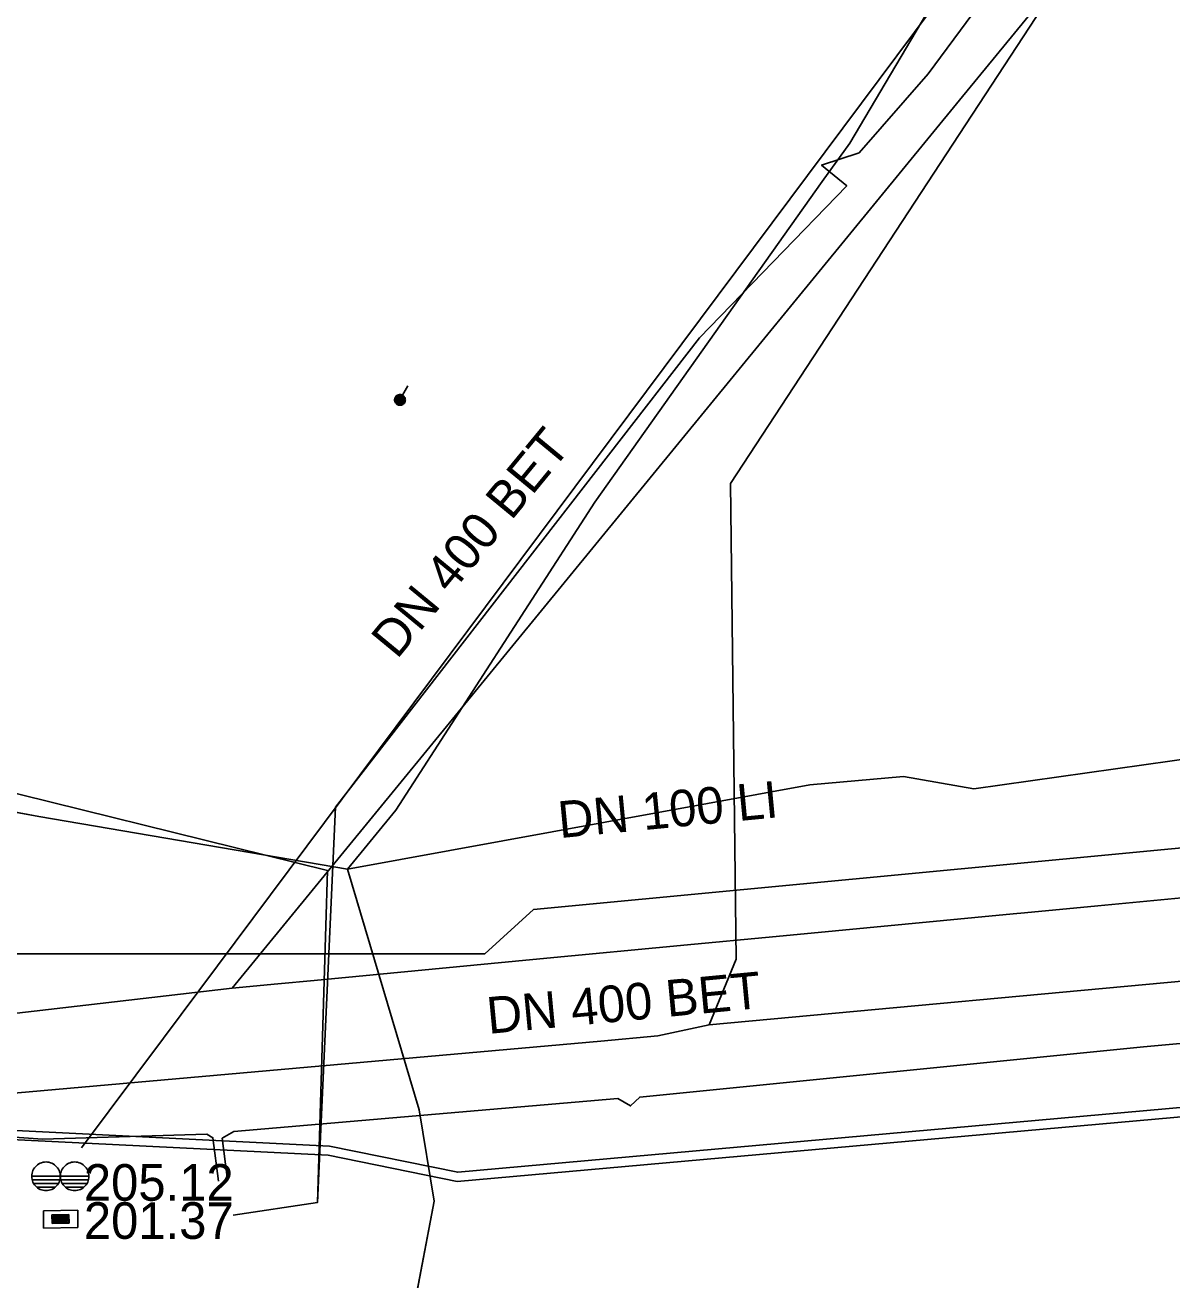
# Model space of a CAD drawing. Extents: x -596024 to -594475, y -1163820 to -1161957.
# Drawn here: x -595998.28 to -595973.24, y -1163008.77 to -1162981.37 of the extents above; entities that cross this region are included whole.
import ezdxf

# ---------------------------------------------------------------- set-up
doc = ezdxf.new("R2010")
doc.units = 0
for name, color, linetype in [('13', 7, 'Continuous'), ('Vrstva 12', 7, 'Continuous'), ('Vrstva 13', 7, 'Continuous'), ('Vrstva 15', 7, 'Continuous'), ('Vrstva 16', 7, 'Continuous'), ('Vrstva 25', 7, 'Continuous'), ('Vrstva 28', 7, 'Continuous'), ('Vrstva 42', 7, 'Continuous'), ('Vrstva 43', 7, 'Continuous'), ('Vrstva 51', 7, 'Continuous'), ('Vrstva 55', 7, 'Continuous'), ('Vrstva 9', 7, 'Continuous')]:
    doc.layers.add(name, color=color, linetype=linetype)

# ---------------------------------------------------------------- blocks, each defined once
blk = doc.blocks.new('NN500')
at = {"layer": '13'}
for points in [[(-0.001, -0.235), (0.023, -0.234), (0.048, -0.23), (0.071, -0.224), (0.094, -0.215), (0.116, -0.204), (0.137, -0.191), (0.156, -0.175), (0.173, -0.158), (0.189, -0.139), (0.202, -0.118), (0.213, -0.096), (0.222, -0.073), (0.229, -0.049), (0.232, -0.025), (0.234, 0), (0.232, 0.024), (0.229, 0.048), (0.222, 0.072), (0.213, 0.095), (0.202, 0.117), (0.189, 0.138), (0.173, 0.157), (0.156, 0.174), (0.137, 0.19), (0.116, 0.203), (0.094, 0.214), (0.071, 0.223), (0.048, 0.229), (0.023, 0.233), (-0.001, 0.235), (-0.026, 0.233), (-0.05, 0.229), (-0.074, 0.223), (-0.097, 0.214), (-0.119, 0.203), (-0.139, 0.19), (-0.158, 0.174), (-0.176, 0.157), (-0.191, 0.138), (-0.205, 0.117), (-0.216, 0.095), (-0.225, 0.072), (-0.231, 0.048), (-0.235, 0.024), (-0.236, 0), (-0.235, -0.025), (-0.231, -0.049), (-0.225, -0.073), (-0.216, -0.096), (-0.205, -0.118), (-0.191, -0.139), (-0.176, -0.158), (-0.158, -0.175), (-0.139, -0.191), (-0.119, -0.204), (-0.097, -0.215), (-0.074, -0.224), (-0.05, -0.23), (-0.026, -0.234), (-0.001, -0.235)], [(-0.001, -0.235), (0.023, -0.234), (0.048, -0.23), (0.071, -0.224), (0.094, -0.215), (0.116, -0.204), (0.137, -0.191), (0.156, -0.175), (0.173, -0.158), (0.189, -0.139), (0.202, -0.118), (0.213, -0.096), (0.222, -0.073), (0.229, -0.049), (0.232, -0.025), (0.234, 0), (0.232, 0.024), (0.229, 0.048), (0.222, 0.072), (0.213, 0.095), (0.202, 0.117), (0.189, 0.138), (0.173, 0.157), (0.156, 0.174), (0.137, 0.19), (0.116, 0.203), (0.094, 0.214), (0.071, 0.223), (0.048, 0.229), (0.023, 0.233), (-0.001, 0.235), (-0.026, 0.233), (-0.05, 0.229), (-0.074, 0.223), (-0.097, 0.214), (-0.119, 0.203), (-0.139, 0.19), (-0.158, 0.174), (-0.176, 0.157), (-0.191, 0.138), (-0.205, 0.117), (-0.216, 0.095), (-0.225, 0.072), (-0.231, 0.048), (-0.235, 0.024), (-0.236, 0), (-0.235, -0.025), (-0.231, -0.049), (-0.225, -0.073), (-0.216, -0.096), (-0.205, -0.118), (-0.191, -0.139), (-0.176, -0.158), (-0.158, -0.175), (-0.139, -0.191), (-0.119, -0.204), (-0.097, -0.215), (-0.074, -0.224), (-0.05, -0.23), (-0.026, -0.234), (-0.001, -0.235)], [(-0.001, -0.206), (0.02, -0.205), (0.041, -0.201), (0.062, -0.196), (0.082, -0.188), (0.101, -0.178), (0.12, -0.167), (0.136, -0.153), (0.151, -0.138), (0.165, -0.121), (0.177, -0.103), (0.186, -0.084), (0.194, -0.064), (0.2, -0.043), (0.203, -0.022), (0.204, 0), (0.203, 0.021), (0.2, 0.042), (0.194, 0.063), (0.186, 0.083), (0.177, 0.102), (0.165, 0.12), (0.151, 0.137), (0.136, 0.152), (0.12, 0.166), (0.101, 0.177), (0.082, 0.187), (0.062, 0.195), (0.041, 0.2), (0.02, 0.204), (-0.001, 0.205), (-0.023, 0.204), (-0.044, 0.2), (-0.065, 0.195), (-0.085, 0.187), (-0.104, 0.177), (-0.122, 0.166), (-0.139, 0.152), (-0.154, 0.137), (-0.167, 0.12), (-0.179, 0.102), (-0.189, 0.083), (-0.197, 0.063), (-0.202, 0.042), (-0.205, 0.021), (-0.207, 0), (-0.205, -0.022), (-0.202, -0.043), (-0.197, -0.064), (-0.189, -0.084), (-0.179, -0.103), (-0.167, -0.121), (-0.154, -0.138), (-0.139, -0.153), (-0.122, -0.167), (-0.104, -0.178), (-0.085, -0.188), (-0.065, -0.196), (-0.044, -0.201), (-0.023, -0.205), (-0.001, -0.206)], [(-0.001, -0.176), (0.017, -0.175), (0.035, -0.172), (0.053, -0.168), (0.07, -0.161), (0.087, -0.153), (0.102, -0.143), (0.116, -0.131), (0.129, -0.118), (0.141, -0.104), (0.151, -0.088), (0.159, -0.072), (0.166, -0.055), (0.171, -0.037), (0.174, -0.019), (0.175, 0), (0.174, 0.018), (0.171, 0.036), (0.166, 0.054), (0.159, 0.071), (0.151, 0.087), (0.141, 0.103), (0.129, 0.117), (0.116, 0.13), (0.102, 0.142), (0.087, 0.152), (0.07, 0.16), (0.053, 0.167), (0.035, 0.172), (0.017, 0.174), (-0.001, 0.175), (-0.02, 0.174), (-0.038, 0.172), (-0.056, 0.167), (-0.073, 0.16), (-0.089, 0.152), (-0.105, 0.142), (-0.119, 0.13), (-0.132, 0.117), (-0.143, 0.103), (-0.153, 0.087), (-0.162, 0.071), (-0.168, 0.054), (-0.173, 0.036), (-0.176, 0.018), (-0.177, 0), (-0.176, -0.019), (-0.173, -0.037), (-0.168, -0.055), (-0.162, -0.072), (-0.153, -0.088), (-0.143, -0.104), (-0.132, -0.118), (-0.119, -0.131), (-0.105, -0.143), (-0.089, -0.153), (-0.073, -0.161), (-0.056, -0.168), (-0.038, -0.172), (-0.02, -0.175), (-0.001, -0.176)], [(-0.001, -0.147), (0.014, -0.146), (0.029, -0.143), (0.044, -0.139), (0.058, -0.134), (0.072, -0.127), (0.085, -0.119), (0.097, -0.109), (0.107, -0.098), (0.117, -0.086), (0.125, -0.073), (0.132, -0.06), (0.138, -0.046), (0.142, -0.031), (0.144, -0.016), (0.145, 0), (0.144, 0.015), (0.142, 0.03), (0.138, 0.045), (0.132, 0.059), (0.125, 0.073), (0.117, 0.086), (0.107, 0.097), (0.097, 0.108), (0.085, 0.118), (0.072, 0.126), (0.058, 0.133), (0.044, 0.139), (0.029, 0.143), (0.014, 0.145), (-0.001, 0.146), (-0.017, 0.145), (-0.032, 0.143), (-0.046, 0.139), (-0.061, 0.133), (-0.074, 0.126), (-0.087, 0.118), (-0.099, 0.108), (-0.11, 0.097), (-0.119, 0.086), (-0.128, 0.073), (-0.135, 0.059), (-0.14, 0.045), (-0.144, 0.03), (-0.147, 0.015), (-0.147, 0), (-0.147, -0.016), (-0.144, -0.031), (-0.14, -0.046), (-0.135, -0.06), (-0.128, -0.073), (-0.119, -0.086), (-0.11, -0.098), (-0.099, -0.109), (-0.087, -0.119), (-0.074, -0.127), (-0.061, -0.134), (-0.046, -0.139), (-0.032, -0.143), (-0.017, -0.146), (-0.001, -0.147)], [(-0.001, -0.117), (0.011, -0.116), (0.023, -0.114), (0.035, -0.111), (0.046, -0.107), (0.057, -0.101), (0.067, -0.095), (0.077, -0.087), (0.085, -0.078), (0.093, -0.069), (0.1, -0.059), (0.105, -0.048), (0.11, -0.036), (0.113, -0.025), (0.115, -0.013), (0.115, 0), (0.115, 0.012), (0.113, 0.024), (0.11, 0.036), (0.105, 0.047), (0.1, 0.058), (0.093, 0.068), (0.085, 0.078), (0.077, 0.086), (0.067, 0.094), (0.057, 0.101), (0.046, 0.106), (0.035, 0.11), (0.023, 0.114), (0.011, 0.116), (-0.001, 0.116), (-0.013, 0.116), (-0.025, 0.114), (-0.037, 0.11), (-0.049, 0.106), (-0.059, 0.101), (-0.07, 0.094), (-0.079, 0.086), (-0.088, 0.078), (-0.096, 0.068), (-0.102, 0.058), (-0.108, 0.047), (-0.112, 0.036), (-0.115, 0.024), (-0.117, 0.012), (-0.118, 0), (-0.117, -0.013), (-0.115, -0.025), (-0.112, -0.036), (-0.108, -0.048), (-0.102, -0.059), (-0.096, -0.069), (-0.088, -0.078), (-0.079, -0.087), (-0.07, -0.095), (-0.059, -0.101), (-0.049, -0.107), (-0.037, -0.111), (-0.025, -0.114), (-0.013, -0.116), (-0.001, -0.117)], [(-0.001, -0.087), (0.008, -0.087), (0.017, -0.085), (0.026, -0.083), (0.034, -0.08), (0.042, -0.076), (0.05, -0.071), (0.057, -0.065), (0.063, -0.059), (0.069, -0.051), (0.074, -0.044), (0.078, -0.036), (0.081, -0.027), (0.084, -0.019), (0.085, -0.01), (0.086, 0), (0.085, 0.009), (0.084, 0.018), (0.081, 0.026), (0.078, 0.035), (0.074, 0.043), (0.069, 0.051), (0.063, 0.058), (0.057, 0.064), (0.05, 0.07), (0.042, 0.075), (0.034, 0.079), (0.026, 0.082), (0.017, 0.085), (0.008, 0.086), (-0.001, 0.087), (-0.01, 0.086), (-0.019, 0.085), (-0.028, 0.082), (-0.037, 0.079), (-0.045, 0.075), (-0.052, 0.07), (-0.059, 0.064), (-0.066, 0.058), (-0.072, 0.051), (-0.077, 0.043), (-0.081, 0.035), (-0.084, 0.026), (-0.086, 0.018), (-0.088, 0.009), (-0.088, 0), (-0.088, -0.01), (-0.086, -0.019), (-0.084, -0.027), (-0.081, -0.036), (-0.077, -0.044), (-0.072, -0.052), (-0.066, -0.059), (-0.059, -0.065), (-0.052, -0.071), (-0.045, -0.076), (-0.037, -0.08), (-0.028, -0.083), (-0.019, -0.085), (-0.01, -0.087), (-0.001, -0.087)], [(-0.001, -0.058), (0.005, -0.057), (0.011, -0.056), (0.016, -0.055), (0.022, -0.053), (0.027, -0.05), (0.032, -0.047), (0.037, -0.043), (0.041, -0.039), (0.045, -0.034), (0.048, -0.029), (0.051, -0.024), (0.053, -0.018), (0.055, -0.012), (0.056, -0.006), (0.056, 0), (0.056, 0.006), (0.055, 0.011), (0.053, 0.017), (0.051, 0.023), (0.048, 0.028), (0.045, 0.033), (0.041, 0.038), (0.037, 0.042), (0.032, 0.046), (0.027, 0.049), (0.022, 0.052), (0.016, 0.054), (0.011, 0.056), (0.005, 0.057), (-0.001, 0.057), (-0.007, 0.057), (-0.013, 0.056), (-0.019, 0.054), (-0.025, 0.052), (-0.03, 0.049), (-0.035, 0.046), (-0.04, 0.042), (-0.044, 0.038), (-0.048, 0.033), (-0.051, 0.028), (-0.054, 0.023), (-0.056, 0.017), (-0.057, 0.011), (-0.058, 0.006), (-0.059, 0), (-0.058, -0.006), (-0.057, -0.012), (-0.056, -0.018), (-0.054, -0.024), (-0.051, -0.029), (-0.048, -0.034), (-0.044, -0.039), (-0.04, -0.043), (-0.035, -0.047), (-0.03, -0.05), (-0.025, -0.053), (-0.019, -0.055), (-0.013, -0.056), (-0.007, -0.057), (-0.001, -0.058)], [(-0.001, -0.028), (0.002, -0.028), (0.005, -0.028), (0.007, -0.027), (0.01, -0.026), (0.013, -0.024), (0.015, -0.023), (0.017, -0.021), (0.019, -0.019), (0.021, -0.017), (0.023, -0.014), (0.024, -0.012), (0.025, -0.009), (0.026, -0.006), (0.026, -0.003), (0.027, 0), (0.026, 0.002), (0.026, 0.005), (0.025, 0.008), (0.024, 0.011), (0.023, 0.013), (0.021, 0.016), (0.019, 0.018), (0.017, 0.02), (0.015, 0.022), (0.013, 0.024), (0.01, 0.025), (0.007, 0.026), (0.005, 0.027), (0.002, 0.027), (-0.001, 0.027), (-0.004, 0.027), (-0.007, 0.027), (-0.01, 0.026), (-0.012, 0.025), (-0.015, 0.024), (-0.018, 0.022), (-0.02, 0.02), (-0.022, 0.018), (-0.024, 0.016), (-0.025, 0.013), (-0.027, 0.011), (-0.028, 0.008), (-0.028, 0.005), (-0.029, 0.002), (-0.029, 0), (-0.029, -0.003), (-0.028, -0.006), (-0.028, -0.009), (-0.027, -0.012), (-0.025, -0.014), (-0.024, -0.017), (-0.022, -0.019), (-0.02, -0.021), (-0.018, -0.023), (-0.015, -0.024), (-0.012, -0.026), (-0.01, -0.027), (-0.007, -0.028), (-0.004, -0.028), (-0.001, -0.028)], [(0.234, 0), (0.704, 0)]]:
    blk.add_lwpolyline(points, dxfattribs=at)
blk = doc.blocks.new('NN450')
at = {"layer": '13'}
for points in [[(0, 0), (-0.003, 0.065), (-0.013, 0.13), (-0.031, 0.193), (-0.054, 0.254), (-0.084, 0.312), (-0.119, 0.367), (-0.161, 0.418), (-0.207, 0.464), (-0.258, 0.505), (-0.313, 0.541), (-0.371, 0.571), (-0.432, 0.594), (-0.495, 0.611), (-0.559, 0.621), (-0.625, 0.625), (-0.69, 0.621), (-0.755, 0.611), (-0.818, 0.594), (-0.879, 0.571), (-0.938, 0.541), (-0.992, 0.505), (-1.043, 0.464), (-1.089, 0.418), (-1.13, 0.367), (-1.166, 0.312), (-1.196, 0.254), (-1.219, 0.193), (-1.236, 0.13), (-1.246, 0.065), (-1.25, 0), (-1.246, -0.066), (-1.236, -0.13), (-1.219, -0.193), (-1.196, -0.255), (-1.166, -0.313), (-1.13, -0.368), (-1.089, -0.419), (-1.043, -0.465), (-0.992, -0.506), (-0.937, -0.542), (-0.879, -0.571), (-0.818, -0.595), (-0.755, -0.612), (-0.69, -0.622), (-0.625, -0.625), (-0.559, -0.622), (-0.495, -0.612), (-0.432, -0.595), (-0.37, -0.571), (-0.312, -0.542), (-0.258, -0.506), (-0.207, -0.465), (-0.161, -0.419), (-0.119, -0.368), (-0.084, -0.313), (-0.054, -0.254), (-0.031, -0.193), (-0.013, -0.13), (-0.003, -0.066), (0, 0)], [(1.25, 0), (1.247, 0.065), (1.237, 0.13), (1.219, 0.193), (1.196, 0.254), (1.166, 0.312), (1.131, 0.367), (1.089, 0.418), (1.043, 0.464), (0.992, 0.505), (0.937, 0.541), (0.879, 0.571), (0.818, 0.594), (0.755, 0.611), (0.691, 0.621), (0.625, 0.625), (0.56, 0.621), (0.495, 0.611), (0.432, 0.594), (0.371, 0.571), (0.312, 0.541), (0.258, 0.505), (0.207, 0.464), (0.161, 0.418), (0.12, 0.367), (0.084, 0.312), (0.054, 0.254), (0.031, 0.193), (0.014, 0.13), (0.004, 0.065), (0, 0), (0.004, -0.066), (0.014, -0.13), (0.031, -0.193), (0.054, -0.255), (0.084, -0.313), (0.12, -0.368), (0.161, -0.419), (0.207, -0.465), (0.258, -0.506), (0.313, -0.542), (0.371, -0.571), (0.432, -0.595), (0.495, -0.612), (0.56, -0.622), (0.625, -0.625), (0.691, -0.622), (0.755, -0.612), (0.818, -0.595), (0.88, -0.571), (0.938, -0.542), (0.992, -0.506), (1.043, -0.465), (1.089, -0.419), (1.131, -0.368), (1.166, -0.313), (1.196, -0.254), (1.219, -0.193), (1.237, -0.13), (1.247, -0.066), (1.25, 0)], [(-1.25, 0), (1.25, 0)], [(-1.23, -0.158), (-0.02, -0.158)], [(-1.161, -0.315), (-0.088, -0.315)], [(-1.033, -0.473), (-0.216, -0.473)], [(0.02, -0.158), (1.23, -0.158)], [(0.089, -0.315), (1.162, -0.315)], [(0.217, -0.473), (1.034, -0.473)]]:
    blk.add_lwpolyline(points, dxfattribs=at)
blk = doc.blocks.new('NN620')
at = {"layer": 'Vrstva 28'}
for points in [[(0.752, 0.004), (-0.748, 0.004)], [(-0.748, 0.004), (-0.748, -0.746)], [(0.752, -0.746), (0.752, 0.004)], [(0.368, -0.18), (-0.376, -0.18)], [(-0.376, -0.18), (-0.376, -0.558)], [(0.321, -0.227), (-0.329, -0.227)], [(-0.329, -0.227), (-0.329, -0.51)], [(-0.329, -0.51), (0.321, -0.51)], [(0.274, -0.274), (-0.281, -0.274)], [(-0.281, -0.274), (-0.281, -0.463)], [(-0.281, -0.463), (0.274, -0.463)], [(0.227, -0.321), (-0.234, -0.321)], [(-0.234, -0.321), (-0.234, -0.416)], [(-0.234, -0.416), (0.227, -0.416)], [(-0.193, -0.369), (0.185, -0.369)], [(0.227, -0.416), (0.227, -0.321)], [(0.274, -0.463), (0.274, -0.274)], [(0.321, -0.51), (0.321, -0.227)], [(0.368, -0.558), (0.368, -0.18)], [(-0.748, -0.746), (0.752, -0.746)], [(-0.376, -0.558), (0.368, -0.558)]]:
    blk.add_lwpolyline(points, dxfattribs=at)

msp = doc.modelspace()

# ---------------------------------------------------------------- linework, layer by layer
at = {"layer": 'Vrstva 13'}
msp.add_lwpolyline([(-596022.832, -1162998.021), (-596005.425, -1163001.297), (-596003.66, -1163001.651), (-595998.732, -1163001.652), (-595988.242, -1163001.653), (-595987.182, -1163000.686), (-595973.244, -1162999.36), (-595961.169, -1162998.229), (-595948.572, -1162997.021), (-595937.132, -1162995.978)], dxfattribs=at)
at = {"layer": 'Vrstva 16'}
for points in [[(-595982.75, -1163001.77), (-595982.88, -1162991.38), (-595972.32, -1162975.27), (-595958.95, -1162954.17)], [(-596007.93, -1163004.08), (-596001.98, -1163005), (-595985.71, -1163003.56), (-595984.46, -1163003.44), (-595983.34, -1163003.2), (-595971.99, -1163002.15), (-595963.48, -1163001.34), (-595954.05, -1163000.5), (-595949.2, -1163000.21), (-595946.71, -1162999.77), (-595933.26, -1162998.54), (-595930.88, -1162998.19), (-595929.42, -1162998.06), (-595910.58, -1162996.4), (-595906.55, -1162996.02), (-595900.64, -1162995.37)], [(-595983.34, -1163003.2), (-595982.75, -1163001.77)]]:
    msp.add_lwpolyline(points, dxfattribs=at)
at = {"layer": 'Vrstva 25'}
for p, q in [((-595976.499, -1162977.581), (-595980.271, -1162983.953)), ((-595980.271, -1162983.953), (-595980.876, -1162984.787)), ((-595980.876, -1162984.787), (-595985.837, -1162991.79)), ((-595985.837, -1162991.79), (-595990.189, -1162998.516)), ((-595977.563, -1162998.049), (-595967.259, -1162996.597)), ((-596003.484, -1162997.626), (-595997.979, -1162998.655)), ((-595981.147, -1162997.962), (-595979.1, -1162997.779)), ((-595979.1, -1162997.779), (-595977.563, -1162998.049)), ((-595991.239, -1162999.804), (-595981.147, -1162997.962)), ((-595997.979, -1162998.655), (-595991.239, -1162999.804)), ((-595990.189, -1162998.516), (-595991.239, -1162999.804)), ((-595991.239, -1162999.804), (-595989.673, -1163005.056)), ((-595989.673, -1163005.056), (-595989.347, -1163007.053)), ((-595989.347, -1163007.053), (-595990.276, -1163011.905))]:
    msp.add_line(p, q, dxfattribs=at)
msp.add_lwpolyline([(-596024.42, -1162985.641), (-596023.237, -1162985.609), (-596020.944, -1162985.706), (-596022.205, -1162989.863), (-596022.376, -1162991.551), (-596022.268, -1162992.371), (-596019.799, -1162994.146), (-596014.487, -1162995.095), (-596007.51, -1162996.568), (-596003.484, -1162997.626), (-595997.979, -1162998.655), (-595991.239, -1162999.804), (-595989.673, -1163005.056), (-595989.347, -1163007.053), (-595990.276, -1163011.905)], dxfattribs=at)
at = {"layer": 'Vrstva 42'}
for points in [[(-596001.179, -1163005.878), (-596001.118, -1163005.375), (-595991.637, -1163005.851), (-595988.834, -1163006.419), (-595972.4, -1163004.95), (-595963.67, -1163004.02), (-595944.189, -1163002.2), (-595944.99, -1162995), (-595945.587, -1162992.845), (-595945.86, -1162992.44), (-595946.275, -1162991.8), (-595946.479, -1162991.626)], [(-596000.981, -1163005.902), (-596000.942, -1163005.585), (-595991.663, -1163006.049), (-595988.846, -1163006.621), (-595972.38, -1163005.15), (-595963.65, -1163004.22), (-595944.171, -1163002.4), (-595942.78, -1163002.28), (-595931.44, -1163001.28), (-595920.349, -1162999.982), (-595919.824, -1163004.454), (-595919.709, -1163004.569), (-595919.624, -1163004.448), (-595920.153, -1162999.937), (-595919.2, -1162999.61), (-595906.12, -1162998.78), (-595905.29, -1162998.32), (-595901.71, -1162997.86), (-595900.28, -1162998.15), (-595894.13, -1162997.39)]]:
    msp.add_lwpolyline(points, dxfattribs=at)
at = {"layer": 'Vrstva 51'}
msp.add_lwpolyline([(-595997.05, -1163005.887), (-595995.26, -1163003.49), (-595977.679, -1162979.94), (-595958.057, -1162953.079)], dxfattribs=at)
at = {"layer": 'Vrstva 55'}
for points in [[(-595993.737, -1163007.36), (-595991.896, -1163007.08), (-595991.68, -1162999.83), (-596000.4, -1162997.68), (-596012.68, -1162994.73), (-596018.57, -1162992.95), (-596015.38, -1162970.85), (-596018.2, -1162967.54), (-596017.59, -1162962.68), (-596013.46, -1162940.69), (-596008.27, -1162917.84), (-596004.5, -1162911.68)], [(-595993.737, -1163007.36), (-595991.896, -1163007.08), (-595991.5, -1162998.45), (-595983.55, -1162988.2), (-595980.336, -1162984.884), (-595980.889, -1162984.429), (-595980.07, -1162984.16), (-595978.56, -1162982.44), (-595973.95, -1162976.21), (-595968.85, -1162967.21), (-595970.45, -1162967.096), (-595968.89, -1162967.14), (-595967.82, -1162965.62), (-595964.9, -1162957.03), (-595963.518, -1162950.624), (-595959.172, -1162950.465)], [(-595993.861, -1163006.587), (-595993.976, -1163005.676), (-595993.72, -1163005.53), (-595985.34, -1163004.81), (-595985.06, -1163004.97), (-595984.86, -1163004.78), (-595973.86, -1163003.685), (-595955.34, -1163001.99), (-595954.95, -1163002.22), (-595954.81, -1163001.95), (-595950.805, -1163001.596), (-595950.603, -1163003.601)], [(-595994.059, -1163006.613), (-595994.179, -1163005.667), (-595994.31, -1163005.59), (-595997.9, -1163005.7), (-596002.81, -1163005.35), (-596007.97, -1163004.66), (-596012.01, -1163004.24), (-596013, -1163004.78), (-596013.34, -1163005.29), (-596012.74, -1163008.7), (-596013.15, -1163009.24), (-596015.43, -1163009.2)]]:
    msp.add_lwpolyline(points, dxfattribs=at)
at = {"layer": 'Vrstva 9'}
msp.add_line((-595993.76, -1163002.404), (-596024.42, -1163005.949), dxfattribs=at)
for points in [[(-595973.873, -1162978.127), (-595977.873, -1162983.01), (-595993.76, -1163002.404)], [(-595937.271, -1162997.015), (-595939.76, -1162997.252), (-595941.775, -1162997.445), (-595942.408, -1162997.505), (-595944.115, -1162997.668), (-595948.326, -1162998.07), (-595954.14, -1162998.624), (-595954.164, -1162998.627), (-595960.601, -1162999.241), (-595963.134, -1162999.482), (-595965.844, -1162999.741), (-595970.426, -1163000.178), (-595971.187, -1163000.251), (-595974.851, -1163000.6), (-595976.455, -1163000.753), (-595976.706, -1163000.777), (-595981.424, -1163001.227), (-595982.113, -1163001.293), (-595983.666, -1163001.441), (-595987.195, -1163001.778), (-595991.966, -1163002.233), (-595992.765, -1163002.309), (-595993.76, -1163002.404)]]:
    msp.add_lwpolyline(points, dxfattribs=at)

# ---------------------------------------------------------------- block references
at = {"layer": 'Vrstva 43', "xscale": 0.5, "yscale": 0.5}
for name, p, rotation in [('NN500', (-595990.095, -1162989.557), 61), ('NN620', (-595997.51, -1163007.258), 1)]:
    msp.add_blockref(name, p, dxfattribs=dict(at, rotation=rotation))
msp.add_blockref('NN450', (-595997.513, -1163006.508), dxfattribs=at)

# ---------------------------------------------------------------- texts
at = {"layer": 'Vrstva 12'}
for rotation, p in [(50.5142, (-595990.161, -1162995.237)), (5.4366, (-595988.161, -1163003.4))]:
    msp.add_text('DN 400 BET', height=0.8, rotation=rotation, dxfattribs=at).set_placement(p)
for s, p in [('205.12', (-595996.999, -1163007.042)), ('201.37', (-595996.999, -1163007.874))]:
    msp.add_text(s, height=0.8, dxfattribs=at).set_placement(p)
at = {"layer": 'Vrstva 15'}
msp.add_text('DN 100 LI', height=0.8, rotation=5.4431, dxfattribs=at).set_placement((-595986.605, -1162999.125))

doc.saveas('drawing.dxf')
